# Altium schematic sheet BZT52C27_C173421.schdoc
size 127 x 101 mm
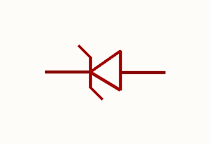
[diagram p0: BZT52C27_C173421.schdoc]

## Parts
D?  bzt52c27_c173421  [SOD-123_L2.7-W1.6-LS3.7-RD]  (value not drawn)

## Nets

Not connected (* = marked no-connect by the designer): D? 1(C) 2(A)

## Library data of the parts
D? = bzt52c27_c173421: 二极管配置:1个独立式;稳压值(标称值):27V;稳压值(范围值):25.65V~28.35V;耗散功率(Pd):500mW;; Manufacturer: MDD(辰达半导体); AddInBom: yes; ModelId: ad7e39f9e5534b3c96ffdc5532ebb493; ModelName: SOD-123_L2.7-W1.6-H1.4-LS3.7; ModelTransform: 146.026,62.992,0,180,0,0,0.0005,0,0; Diode Configuration: 1个独立式; Zener Voltage(Nom): 27V; Reverse Leakage Current (Ir): 100nA@21V; Pd - Power Dissipation: 500mW; Impedance(Zzt): 70Ω; Tolerance: ±5%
